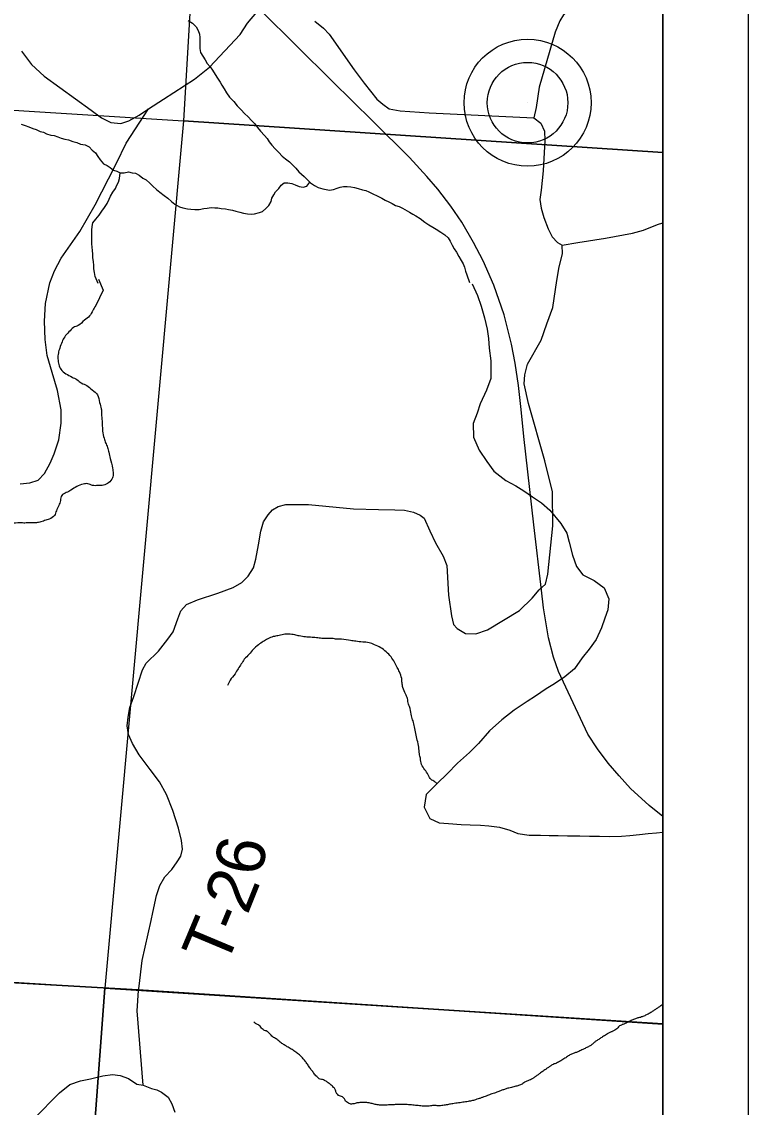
# Model space of a CAD drawing. Extents: x -13.7 to 34, y 0 to 32.3.
# Drawn here: x 29.565 to 30.417, y 14.638 to 15.91 of the extents above; entities that cross this region are included whole.
import ezdxf

# ---------------------------------------------------------------- set-up
doc = ezdxf.new("R2010")
doc.units = 0
for name, color, linetype in [('GM_X_Corporation', 7, 'Continuous'), ('GM_X_County_Road', 7, 'Continuous'), ('GM_X_Major_River', 7, 'Continuous'), ('GM_X_Minor_River', 7, 'Continuous'), ('GM_X_Rail_Line', 7, 'Continuous'), ('GM_X_Township_Road', 7, 'Continuous'), ('GM_X_Township_Road_Text', 7, 'Continuous'), ('GM_X_Unincorporated', 7, 'Continuous'), ('GM_X_Unincorporated_Location', 7, 'Continuous'), ('SH_Data', 7, 'Continuous')]:
    doc.layers.add(name, color=color, linetype=linetype)

msp = doc.modelspace()

# ---------------------------------------------------------------- linework, layer by layer
at = {"layer": 'GM_X_Corporation'}
for points in [[(25.5491, 14.1), (30.3167, 14.1), (30.3167, 20.877), (30.2775, 20.8796), (29.9598, 20.9), (26.0026, 20.9)], [(27.6886, 14.8962), (28.6553, 14.8354), (29.7019, 14.7755), (30.3167, 14.7354), (30.3167, 20.877), (30.2775, 20.8796), (29.9598, 20.9), (26.0026, 20.9)]]:
    msp.add_lwpolyline(points, dxfattribs=at)
for points in [[(30.3167, 15.7567), (30.3167, 16.7776), (30.2872, 16.7795), (29.8135, 16.8087), (29.8095, 16.7223), (29.7836, 16.2855), (29.7549, 15.7939)], [(28.7402, 15.8562), (28.7512, 15.8567), (29.7549, 15.7939), (29.6625, 14.7774), (28.6615, 14.8398)], [(30.3167, 14.7358), (30.3167, 15.7567), (29.7549, 15.7939), (29.6625, 14.7774)], [(25.5491, 14.1), (30.3167, 14.1), (30.3167, 14.7354), (29.7019, 14.7755), (28.6553, 14.8354), (27.6886, 14.8962), (26.847, 14.9399), (26.2581, 14.9774), (25.6174, 15.0182)], [(28.6073, 14.1), (29.6122, 14.1), (29.6625, 14.7774), (28.6615, 14.8398)], [(29.6122, 14.1), (30.3167, 14.1), (30.3167, 14.7358), (29.6625, 14.7774)]]:
    msp.add_lwpolyline(points, close=True, dxfattribs=at)
at = {"layer": 'GM_X_County_Road'}
for points in [[(30.286, 16.1976), (30.2847, 16.18), (30.284, 16.1453), (30.2864, 16.1225), (30.2888, 16.1013), (30.2951, 16.0738), (30.3076, 16.0408), (30.3114, 16.0306), (30.3128, 16.0234), (30.3119, 16.016), (30.3103, 16.0093), (30.3057, 16.0016), (30.2967, 15.994), (30.2801, 15.984), (30.2559, 15.9688), (30.239, 15.9576), (30.2103, 15.9301), (30.2002, 15.9179), (30.196, 15.9111), (30.1903, 15.8978), (30.1716, 15.8333), (30.168, 15.8093), (30.1652, 15.7975)], [(29.565, 15.8754), (29.5769, 15.86), (29.5915, 15.8461), (29.6467, 15.8065), (29.6586, 15.7974), (29.6696, 15.792), (29.6813, 15.7909), (29.6909, 15.7939), (29.703, 15.8004), (29.714, 15.8079), (29.7313, 15.8193), (29.7677, 15.8427), (29.7852, 15.8567), (29.8211, 15.8952), (29.8297, 15.9081), (29.8409, 15.921)], [(29.9089, 15.9105), (29.9188, 15.9025), (29.9256, 15.8955), (29.955, 15.8535), (29.9665, 15.8381), (29.9813, 15.8193), (29.9883, 15.8133), (29.9958, 15.8079), (30.0089, 15.8054), (30.0429, 15.8032), (30.1652, 15.7975)], [(29.5793, 14.6243), (29.6096, 14.6548), (29.6215, 14.6647), (29.6341, 14.6691), (29.6458, 14.6712), (29.6603, 14.6749), (29.6717, 14.6763), (29.6808, 14.6754), (29.6904, 14.6719), (29.7002, 14.6651), (29.7074, 14.664), (29.7175, 14.6602), (29.7236, 14.6586), (29.7292, 14.6558), (29.7369, 14.6499), (29.7411, 14.642), (29.7446, 14.6324)]]:
    msp.add_lwpolyline(points, dxfattribs=at)
at = {"layer": 'GM_X_Major_River'}
msp.add_lwpolyline([(30.0931, 15.6027), (30.0992, 15.589), (30.1038, 15.5765), (30.1077, 15.5629), (30.1108, 15.5496), (30.1123, 15.5387), (30.1131, 15.5273), (30.1151, 15.5125), (30.1151, 15.5026), (30.1148, 15.492), (30.1099, 15.4783), (30.1024, 15.4624), (30.0991, 15.4514), (30.0942, 15.4392), (30.0946, 15.4233), (30.1012, 15.4081), (30.1103, 15.3945), (30.1183, 15.3832), (30.1327, 15.3726), (30.1441, 15.3662), (30.1536, 15.3602), (30.1639, 15.3531), (30.1745, 15.3463), (30.184, 15.3376), (30.197, 15.3221), (30.2039, 15.3108), (30.2069, 15.3002), (30.2108, 15.285), (30.2154, 15.2718), (30.2226, 15.2619), (30.2359, 15.2552), (30.2477, 15.2465), (30.2531, 15.2336), (30.252, 15.2207), (30.2486, 15.2112), (30.2445, 15.1998), (30.2385, 15.1861), (30.2302, 15.1747), (30.2219, 15.1645), (30.2129, 15.1519), (30.2016, 15.1424), (30.1895, 15.1343), (30.1797, 15.1282), (30.1672, 15.1198), (30.1574, 15.1133), (30.1423, 15.1034), (30.1279, 15.092), (30.1136, 15.079), (30.1004, 15.0642), (30.0898, 15.0539), (30.0759, 15.0413), (30.0638, 15.0287), (30.0521, 15.0173), (30.0393, 15.0047), (30.0367, 14.9895), (30.0436, 14.9763), (30.0546, 14.9714), (30.0652, 14.9707), (30.0804, 14.9693), (30.0906, 14.9689), (30.1027, 14.9686), (30.1126, 14.9679), (30.1251, 14.9664), (30.1372, 14.9627), (30.1467, 14.9589), (30.16, 14.9567), (30.1732, 14.9568), (30.1834, 14.9564), (30.1937, 14.9565), (30.205, 14.9562), (30.2191, 14.9562), (30.2304, 14.9555), (30.2425, 14.9556), (30.2539, 14.9553), (30.2679, 14.9557), (30.2778, 14.9565), (30.2891, 14.9577), (30.2993, 14.9589), (30.3092, 14.9597), (30.3167, 14.9602)], dxfattribs=at)
at = {"layer": 'GM_X_Minor_River'}
for points in [[(29.7604, 15.9116), (29.7653, 15.9082), (29.7695, 15.9041), (29.7722, 15.8995), (29.7737, 15.8953), (29.7741, 15.8916), (29.7741, 15.887), (29.7738, 15.8832), (29.7738, 15.8787), (29.7749, 15.8741), (29.7776, 15.8696), (29.7803, 15.8654), (29.7825, 15.8612), (29.786, 15.8571), (29.789, 15.8533)], [(29.789, 15.8533), (29.7921, 15.8483), (29.7947, 15.8438), (29.7978, 15.8392), (29.7997, 15.8355), (29.8024, 15.8313), (29.8054, 15.8267), (29.8089, 15.8214), (29.8138, 15.8165), (29.8176, 15.8116), (29.8226, 15.8067), (29.8264, 15.8025), (29.8306, 15.7987), (29.8344, 15.7942), (29.8382, 15.7908), (29.8416, 15.7862), (29.845, 15.7817), (29.8496, 15.7768), (29.8527, 15.773), (29.8553, 15.7692), (29.8584, 15.7654), (29.8622, 15.7609), (29.8664, 15.7567), (29.8706, 15.7525), (29.8744, 15.7495), (29.8789, 15.7457), (29.8827, 15.7423), (29.8866, 15.7382), (29.89, 15.734), (29.8961, 15.7287), (29.8999, 15.7253), (29.9037, 15.7211), (29.9083, 15.7181), (29.9128, 15.7158), (29.9181, 15.714), (29.9219, 15.7132), (29.9261, 15.7128), (29.9307, 15.7132), (29.9348, 15.7148), (29.9386, 15.7163), (29.9424, 15.7171), (29.9466, 15.7171), (29.9508, 15.7167), (29.9553, 15.7159), (29.9595, 15.7144), (29.9645, 15.7129), (29.9683, 15.7122), (29.9721, 15.7107), (29.9766, 15.7084), (29.9816, 15.7061), (29.9873, 15.7031), (29.9911, 15.7009), (29.9956, 15.699), (29.9994, 15.6971), (30.0033, 15.6948), (30.0074, 15.6933), (30.0116, 15.6914), (30.0196, 15.6869), (30.0234, 15.6846), (30.0272, 15.6824), (30.0322, 15.6793), (30.0375, 15.6752), (30.0424, 15.6718), (30.047, 15.6691), (30.0508, 15.6669), (30.0565, 15.6635), (30.0611, 15.6601), (30.0649, 15.6566), (30.0672, 15.6529), (30.0698, 15.6483), (30.0721, 15.6438), (30.0748, 15.64), (30.0775, 15.6347), (30.0801, 15.6301), (30.0824, 15.6263), (30.084, 15.6222), (30.0851, 15.6176), (30.087, 15.6134), (30.0901, 15.6046)], [(29.5648, 15.7901), (29.5693, 15.7882), (29.5735, 15.7867), (29.5781, 15.7848), (29.5823, 15.7837), (29.5868, 15.7814), (29.5906, 15.7807), (29.5944, 15.7788), (29.5994, 15.7769), (29.6032, 15.7765), (29.6077, 15.775), (29.6115, 15.7735), (29.6157, 15.7724), (29.6199, 15.7716), (29.6252, 15.7698), (29.6298, 15.7683), (29.6343, 15.7667), (29.6396, 15.7656), (29.6442, 15.7634), (29.648, 15.7596), (29.6518, 15.7562), (29.6545, 15.752), (29.6572, 15.7482), (29.661, 15.7433), (29.6652, 15.7414), (29.669, 15.7391), (29.6728, 15.7361), (29.6766, 15.735), (29.6807, 15.7331), (29.6853, 15.7331), (29.6902, 15.7339), (29.6948, 15.7331), (29.6986, 15.7324), (29.7028, 15.7301), (29.707, 15.7267), (29.7112, 15.7248), (29.7153, 15.721), (29.7188, 15.7173), (29.7233, 15.7135), (29.7271, 15.7101), (29.7321, 15.7063), (29.7363, 15.7033), (29.7408, 15.6995), (29.7446, 15.6964), (29.75, 15.693), (29.7542, 15.6919), (29.7595, 15.6908), (29.7636, 15.6904), (29.7682, 15.6901), (29.7731, 15.6901), (29.7788, 15.6912), (29.7826, 15.6916), (29.7872, 15.6924), (29.7914, 15.692), (29.7952, 15.692), (29.799, 15.6913), (29.8039, 15.6909), (29.8077, 15.6898), (29.8123, 15.689), (29.8161, 15.6879), (29.821, 15.6868), (29.8252, 15.6856), (29.8297, 15.6849)], [(29.6549, 15.6031), (29.6515, 15.6116), (29.6507, 15.6162), (29.6499, 15.6203), (29.6499, 15.6245), (29.6495, 15.629), (29.6487, 15.6332), (29.6484, 15.6378), (29.6483, 15.6419), (29.648, 15.6457), (29.6476, 15.6499), (29.6475, 15.6556), (29.6475, 15.6621), (29.6475, 15.6658), (29.6479, 15.67), (29.6486, 15.6742), (29.652, 15.6788), (29.6562, 15.6833), (29.6592, 15.6879), (29.6623, 15.6924), (29.6653, 15.697), (29.6679, 15.7019), (29.6694, 15.7057), (29.6721, 15.7103), (29.6751, 15.7145), (29.6766, 15.7183), (29.6785, 15.7221), (29.68, 15.7263), (29.6807, 15.7331)], [(29.8297, 15.6849), (29.8343, 15.6845), (29.8381, 15.6849), (29.8438, 15.6865), (29.8476, 15.6876), (29.8514, 15.691), (29.8548, 15.6948), (29.8574, 15.6994), (29.8585, 15.7032), (29.8608, 15.707), (29.8627, 15.7108), (29.8665, 15.7146), (29.8691, 15.7184), (29.8729, 15.7211), (29.8771, 15.7211), (29.8817, 15.7203), (29.8858, 15.7188), (29.8904, 15.7169), (29.895, 15.7162), (29.8995, 15.7173), (29.9029, 15.7219)], [(29.6553, 15.6084), (29.6605, 15.5954), (29.652, 15.5773)]]:
    msp.add_lwpolyline(points, dxfattribs=at)
for points in [[(29.652, 15.5773), (29.6485, 15.5716), (29.6447, 15.5652), (29.6389, 15.5603), (29.6313, 15.5539), (29.626, 15.5517), (29.6206, 15.5465), (29.6156, 15.5408), (29.6125, 15.5348), (29.6098, 15.5276), (29.6082, 15.5219), (29.6077, 15.5151), (29.6088, 15.5082), (29.611, 15.5029), (29.6171, 15.4975), (29.6242, 15.4936), (29.6299, 15.4906), (29.6351, 15.4867), (29.6416, 15.4836), (29.648, 15.4786), (29.654, 15.4728), (29.6565, 15.4637), (29.6584, 15.4565), (29.6587, 15.4508), (29.6594, 15.442), (29.6597, 15.436), (29.66, 15.4303), (29.6618, 15.4219), (29.6636, 15.4166), (29.6659, 15.4112), (29.6673, 15.4055), (29.6688, 15.3983), (29.6717, 15.3869), (29.6724, 15.3808), (29.6716, 15.3755), (29.667, 15.3698), (29.6612, 15.3669), (29.6544, 15.3665), (29.6483, 15.3666), (29.6427, 15.3686), (29.6374, 15.3682), (29.6297, 15.3653), (29.6229, 15.3612), (29.6175, 15.3582), (29.6122, 15.3548), (29.6106, 15.3491), (29.6086, 15.3431), (29.6059, 15.337), (29.6036, 15.3314), (29.5975, 15.3273), (29.5921, 15.3254), (29.5864, 15.3236), (29.5811, 15.3229), (29.575, 15.3229), (29.569, 15.3226), (29.5637, 15.3227), (29.5523, 15.322), (29.547, 15.3213), (29.5409, 15.3198), (29.5348, 15.3192), (29.5291, 15.3184), (29.5238, 15.3174), (29.5173, 15.3163), (29.5105, 15.3152), (29.5044, 15.3145), (29.4983, 15.3157), (29.4916, 15.32), (29.4863, 15.3219), (29.4799, 15.3265), (29.4731, 15.33), (29.4666, 15.332), (29.4602, 15.3347), (29.4546, 15.3405), (29.4497, 15.347), (29.4433, 15.3535), (29.4377, 15.3577), (29.4312, 15.3566), (29.4252, 15.3559), (29.4198, 15.3552), (29.4141, 15.3545), (29.4077, 15.3538), (29.4012, 15.3535), (29.3933, 15.354), (29.3879, 15.3525), (29.3826, 15.3507), (29.3761, 15.3477), (29.3697, 15.3459), (29.3609, 15.3418), (29.3548, 15.3388), (29.3491, 15.3347), (29.3441, 15.329), (29.3383, 15.3234), (29.3326, 15.3174), (29.326, 15.3102), (29.3222, 15.305), (29.3176, 15.2997), (29.3153, 15.2944)], [(30.0106, 15.1405), (30.008, 15.1481), (30.0051, 15.1535), (30.0021, 15.1596), (29.998, 15.1657), (29.9859, 15.1765), (29.9788, 15.1799), (29.9723, 15.1823), (29.9648, 15.1831), (29.9568, 15.184), (29.9507, 15.1848), (29.9401, 15.1864), (29.9344, 15.1865), (29.9288, 15.1873), (29.917, 15.1874), (29.9106, 15.1882), (29.9037, 15.1887), (29.8977, 15.1891), (29.8905, 15.1903), (29.8852, 15.1915), (29.878, 15.1923), (29.8719, 15.192), (29.8654, 15.1906), (29.8601, 15.1895), (29.8536, 15.1869), (29.8483, 15.1839), (29.8426, 15.1798), (29.8364, 15.1745), (29.8318, 15.1689), (29.8261, 15.1629), (29.8226, 15.1576), (29.8188, 15.1519), (29.8153, 15.1459), (29.8095, 15.1384), (29.8064, 15.1323)], [(30.0521, 15.0173), (30.0491, 15.0197), (30.0451, 15.0221), (30.0417, 15.0275), (30.0376, 15.0336), (30.0339, 15.0397), (30.0324, 15.0469), (30.0313, 15.0522), (30.0306, 15.0598), (30.0288, 15.0682), (30.027, 15.0758), (30.0256, 15.0838), (30.0238, 15.0907), (30.0219, 15.0967), (30.0205, 15.1051), (30.0186, 15.1104), (30.0172, 15.1169), (30.015, 15.1223), (30.012, 15.1299), (30.0109, 15.1352), (30.0106, 15.1405)]]:
    msp.add_spline(points, degree=3, dxfattribs=at)
msp.add_open_spline([(30.3167, 14.7587), (30.3154, 14.7578), (30.3141, 14.7569), (30.3128, 14.756), (30.3097, 14.7538), (30.3065, 14.7516), (30.3033, 14.7496), (30.2994, 14.7472), (30.2953, 14.7453), (30.2911, 14.7437), (30.2892, 14.743), (30.2872, 14.7429), (30.2854, 14.7422), (30.2833, 14.7414), (30.2813, 14.7405), (30.2793, 14.7396), (30.277, 14.7385), (30.2747, 14.7373), (30.2724, 14.7362), (30.2707, 14.7354), (30.2688, 14.7349), (30.2671, 14.734), (30.2644, 14.7327), (30.2628, 14.7299), (30.2602, 14.7284), (30.2574, 14.7268), (30.2542, 14.7257), (30.2514, 14.7239), (30.2493, 14.7226), (30.2471, 14.7212), (30.2449, 14.7198), (30.2432, 14.7187), (30.2414, 14.7176), (30.2396, 14.7165), (30.2366, 14.7146), (30.2342, 14.7118), (30.2312, 14.7101), (30.2293, 14.709), (30.2274, 14.7081), (30.2255, 14.7071), (30.2229, 14.7058), (30.2204, 14.7046), (30.2178, 14.7034), (30.2161, 14.7026), (30.2143, 14.7022), (30.2125, 14.7015), (30.2105, 14.7008), (30.2086, 14.7), (30.2068, 14.6989), (30.2046, 14.6977), (30.2028, 14.6961), (30.2007, 14.6948), (30.1982, 14.6933), (30.1956, 14.6918), (30.193, 14.6903), (30.1911, 14.6893), (30.1888, 14.6889), (30.1869, 14.6878), (30.1839, 14.6858), (30.181, 14.6838), (30.1782, 14.6818), (30.1762, 14.6804), (30.1743, 14.679), (30.1724, 14.6776), (30.1696, 14.6756), (30.1668, 14.6736), (30.164, 14.6717), (30.1615, 14.6699), (30.1583, 14.6693), (30.1556, 14.6679), (30.1535, 14.6669), (30.1518, 14.6651), (30.1495, 14.6642), (30.1475, 14.6635), (30.1455, 14.6629), (30.1434, 14.6624), (30.1405, 14.6616), (30.1376, 14.661), (30.1347, 14.6602), (30.1328, 14.6596), (30.1309, 14.659), (30.129, 14.6583), (30.1271, 14.6576), (30.1252, 14.6568), (30.1233, 14.6561), (30.1205, 14.6551), (30.1177, 14.6542), (30.1149, 14.6532), (30.1122, 14.6522), (30.1096, 14.6512), (30.1069, 14.6502), (30.1036, 14.649), (30.1003, 14.6479), (30.097, 14.6469), (30.0946, 14.6461), (30.0922, 14.6455), (30.0898, 14.6451), (30.0867, 14.6445), (30.0837, 14.6441), (30.0806, 14.6436), (30.0772, 14.6431), (30.0738, 14.6427), (30.0704, 14.6422), (30.0678, 14.6418), (30.0653, 14.6412), (30.0628, 14.6408), (30.0601, 14.6403), (30.0575, 14.6399), (30.0548, 14.6397), (30.0529, 14.6396), (30.051, 14.6402), (30.0491, 14.6402), (30.0466, 14.6401), (30.0441, 14.6395), (30.0415, 14.6395), (30.0393, 14.6394), (30.037, 14.6393), (30.0347, 14.6395), (30.0315, 14.6398), (30.0284, 14.6401), (30.0252, 14.6404), (30.0219, 14.6407), (30.0187, 14.641), (30.0154, 14.6413), (30.0132, 14.6414), (30.0111, 14.6414), (30.0089, 14.6413), (30.0041, 14.6412), (29.9993, 14.6409), (29.9945, 14.6407), (29.9926, 14.6406), (29.9907, 14.6405), (29.9888, 14.6404), (29.986, 14.6403), (29.9832, 14.6408), (29.9805, 14.6412), (29.9782, 14.6416), (29.976, 14.6424), (29.9736, 14.6428), (29.9709, 14.6433), (29.9681, 14.6436), (29.9653, 14.6437), (29.9633, 14.6437), (29.9613, 14.6435), (29.9592, 14.6433), (29.957, 14.6431), (29.9549, 14.6421), (29.9528, 14.6419), (29.9509, 14.6417), (29.949, 14.6423), (29.9471, 14.6435), (29.9445, 14.645), (29.9439, 14.648), (29.9419, 14.6496), (29.9401, 14.6509), (29.9374, 14.6511), (29.9358, 14.6527), (29.9334, 14.6551), (29.933, 14.6591), (29.9306, 14.6615), (29.9289, 14.6631), (29.9272, 14.6647), (29.9253, 14.6661), (29.9236, 14.6673), (29.9219, 14.6685), (29.9201, 14.6695), (29.9179, 14.6708), (29.9149, 14.6706), (29.9129, 14.6723), (29.9109, 14.674), (29.9092, 14.676), (29.9076, 14.678), (29.9062, 14.6798), (29.9048, 14.6815), (29.9035, 14.6834), (29.9021, 14.6854), (29.9008, 14.6875), (29.8994, 14.6895), (29.8981, 14.6913), (29.8967, 14.6931), (29.8953, 14.6948), (29.8936, 14.6968), (29.8917, 14.6986), (29.8896, 14.7002), (29.8876, 14.7019), (29.8854, 14.7034), (29.8832, 14.7048), (29.881, 14.7063), (29.8787, 14.7077), (29.8764, 14.7091), (29.8747, 14.7101), (29.8729, 14.7111), (29.8712, 14.7122), (29.8691, 14.7135), (29.8675, 14.7153), (29.8655, 14.7168), (29.8636, 14.7182), (29.8614, 14.7192), (29.8595, 14.7206), (29.8573, 14.7223), (29.8557, 14.7247), (29.8535, 14.7264), (29.8519, 14.7276), (29.8498, 14.7279), (29.8482, 14.7291), (29.8461, 14.7306), (29.8448, 14.7332), (29.8426, 14.7345), (29.8408, 14.7355), (29.839, 14.7365), (29.8373, 14.7376)], degree=3, dxfattribs=at)
at = {"layer": 'GM_X_Rail_Line'}
msp.add_lwpolyline([(30.3167, 14.9786), (30.3005, 14.9916), (30.2788, 15.0117), (30.2653, 15.0263), (30.2526, 15.0413), (30.24, 15.0582), (30.2287, 15.0753), (30.1944, 15.1485), (30.1886, 15.1653), (30.1826, 15.1881), (30.1766, 15.2231), (30.1742, 15.244), (30.1655, 15.3203), (30.1536, 15.4239), (30.1506, 15.4556), (30.1473, 15.4836), (30.1433, 15.5099), (30.1393, 15.5323), (30.1306, 15.5666), (30.1186, 15.6013), (30.1058, 15.6298), (30.0946, 15.6511), (30.0808, 15.675), (30.0681, 15.6938), (30.0529, 15.7136), (30.0398, 15.7288), (30.0196, 15.751), (29.9766, 15.7933), (29.9289, 15.8404), (29.8454, 15.9232)], dxfattribs=at)
at = {"layer": 'GM_X_Township_Road'}
for points in [[(29.5636, 15.3685), (29.5748, 15.3695), (29.5846, 15.3727), (29.5921, 15.3807), (29.5986, 15.3926), (29.6031, 15.4035), (29.6087, 15.4201), (29.6115, 15.4397), (29.6115, 15.4551), (29.6071, 15.4778), (29.601, 15.499), (29.5949, 15.5189), (29.5926, 15.5378), (29.5921, 15.5593), (29.5931, 15.5798), (29.5982, 15.6039), (29.6036, 15.6181), (29.6113, 15.633), (29.6334, 15.6643), (29.6512, 15.6954), (29.6668, 15.7257), (29.6764, 15.7442), (29.6878, 15.7677), (29.714, 15.8079)], [(30.1652, 15.7975), (30.1737, 15.7912), (30.178, 15.7818), (30.1784, 15.7709), (30.1763, 15.7352), (30.1741, 15.7125), (30.1722, 15.7018), (30.1741, 15.6915), (30.1769, 15.6804), (30.1821, 15.6675), (30.187, 15.6581), (30.193, 15.6513), (30.1985, 15.6483), (30.2169, 15.6511), (30.2495, 15.6563), (30.2808, 15.6622), (30.2939, 15.6656), (30.3101, 15.6722), (30.3167, 15.6744)], [(29.7188, 14.8662), (29.723, 14.8862), (29.7271, 14.898), (29.733, 14.908), (29.7412, 14.9168), (29.7475, 14.9256), (29.7518, 14.9324), (29.7538, 14.9403), (29.7526, 14.9508), (29.7489, 14.9649), (29.7424, 14.9859), (29.7348, 15.0047), (29.7267, 15.0194), (29.7156, 15.0338), (29.7029, 15.0511), (29.6952, 15.0642), (29.6905, 15.0748), (29.689, 15.0849), (29.6899, 15.0953), (29.6921, 15.1065), (29.6968, 15.1194), (29.7068, 15.1505), (29.7111, 15.1585), (29.7254, 15.1726), (29.7365, 15.1865), (29.7426, 15.1953), (29.7481, 15.2102), (29.7516, 15.2196), (29.7583, 15.2271), (29.7714, 15.2325), (29.7949, 15.2406), (29.8131, 15.2472), (29.8231, 15.2529), (29.8307, 15.2603), (29.837, 15.2701), (29.8397, 15.2801), (29.8428, 15.2971), (29.8456, 15.3132), (29.8487, 15.324), (29.854, 15.3322), (29.8593, 15.3382), (29.8657, 15.342), (29.8747, 15.3445), (29.9012, 15.3443), (29.954, 15.3392), (29.9834, 15.3386), (30.0024, 15.3379), (30.0139, 15.3375), (30.0243, 15.3355), (30.0323, 15.332), (30.037, 15.3281), (30.0435, 15.3134), (30.0501, 15.2993), (30.0591, 15.2838), (30.0636, 15.2729), (30.0654, 15.2382), (30.0689, 15.2137), (30.0713, 15.2038), (30.0756, 15.1989), (30.0852, 15.1932), (30.0973, 15.1928), (30.1112, 15.1973), (30.1486, 15.2202), (30.1635, 15.2345), (30.1717, 15.2443), (30.1791, 15.2511), (30.1819, 15.2625), (30.1876, 15.3193), (30.1874, 15.3592), (30.1782, 15.3954), (30.159, 15.4626), (30.1539, 15.4858), (30.1547, 15.4962), (30.1578, 15.5086), (30.1741, 15.5369), (30.1807, 15.5561), (30.1876, 15.5751), (30.1923, 15.6066), (30.1952, 15.6229), (30.1989, 15.6381), (30.1985, 15.6483)], [(29.7027, 14.7799), (29.7064, 14.8099), (29.7168, 14.8567), (29.7188, 14.8662)], [(29.7074, 14.664), (29.7004, 14.7512), (29.7021, 14.775), (29.7027, 14.7799)]]:
    msp.add_lwpolyline(points, dxfattribs=at)
at = {"layer": 'GM_X_Unincorporated'}
for radius in [0.0744, 0.0472]:
    msp.add_circle((30.158, 15.8151), radius, dxfattribs=at)
at = {"layer": 'GM_X_Unincorporated_Location'}
msp.add_line((30.158, 15.8151), (30.158, 15.8151), dxfattribs=at)
at = {"layer": 'SH_Data'}
for points in [[(23.4167, 21), (30.4167, 21), (30.4167, 14), (23.4167, 14)], [(23.5167, 20.9), (30.3167, 20.9), (30.3167, 14.1), (23.5167, 14.1)]]:
    msp.add_lwpolyline(points, close=True, dxfattribs=at)

# ---------------------------------------------------------------- texts
at = {"layer": 'GM_X_Township_Road_Text'}
for s, rotation, p in [('6', 80.3195, (29.8463, 14.9076)), ('2', 68.1701, (29.8297, 14.8625)), ('-', 67.4238, (29.8205, 14.8402)), ('T', 67.2499, (29.804, 14.8009))]:
    msp.add_text(s, height=0.0568, rotation=rotation, dxfattribs=at).set_placement(p)

doc.saveas('drawing.dxf')
